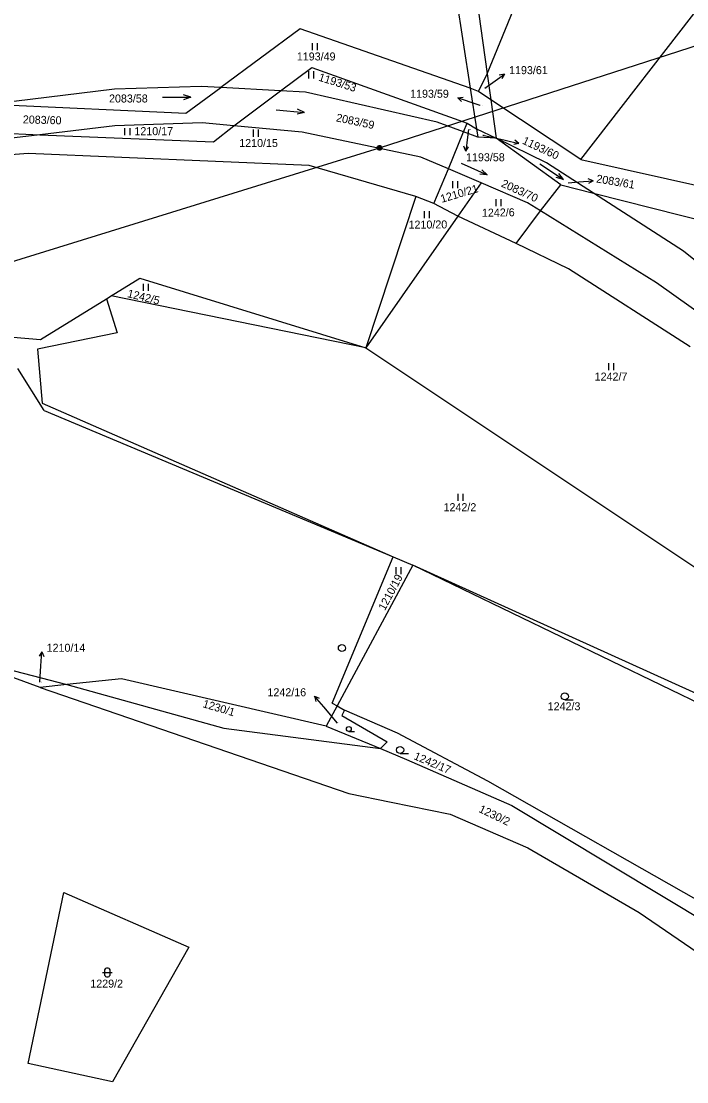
# Model space of a CAD drawing. Extents: x -795483 to -789093, y -1112258 to -1108741.
# Drawn here: x -793189.9 to -793048.5, y -1109580.4 to -1109355.1 of the extents above; entities that cross this region are included whole.
import ezdxf

# ---------------------------------------------------------------- set-up
doc = ezdxf.new("R2010")
doc.units = 0
for name, color, linetype in [('Komunikace', 7, 'Continuous'), ('Vrstva 1', 7, 'Continuous'), ('Vrstva 12', 7, 'Continuous'), ('Vrstva 14', 7, 'Continuous'), ('Vrstva 16', 7, 'Continuous'), ('Vrstva 23', 7, 'Continuous'), ('Vrstva 26', 7, 'Continuous'), ('Vrstva 28', 7, 'Continuous')]:
    doc.layers.add(name, color=color, linetype=linetype)

msp = doc.modelspace()

# ---------------------------------------------------------------- linework, layer by layer
at = {"layer": 'Komunikace'}
for p, q in [((-793091.42, -1109369.35), (-793089.69, -1109368.1)), ((-793092.43, -1109372.97), (-793094.29, -1109372.33)), ((-793094.86, -1109378.12), (-793095.08, -1109379.71)), ((-793091.81, -1109379.3), (-793087.1, -1109380.37)), ((-793073.68, -1109389.4), (-793071.42, -1109389.23)), ((-793185.98, -1109495.5), (-793185.73, -1109492.02)), ((-793122.68, -1109504.19), (-793125.65, -1109500.75))]:
    msp.add_line(p, q, dxfattribs=at)
at = {"layer": 'Vrstva 1'}
for p, q in [((-793109.65, -1109272.48), (-793094.52, -1109369.29)), ((-793103.34, -1109277.28), (-793090.93, -1109366.25)), ((-793090.93, -1109366.25), (-793070.4, -1109316.05)), ((-793071, -1109384.44), (-793038.14, -1109342.1)), ((-793130.64, -1109356.7), (-793147.51, -1109369.19)), ((-793094.52, -1109369.29), (-793130.64, -1109356.7)), ((-793134.83, -1109369.87), (-793128.2, -1109364.91)), ((-793128.2, -1109364.91), (-793095.19, -1109376.73)), ((-793092.76, -1109370), (-793090.93, -1109366.25)), ((-793090.93, -1109366.25), (-793090.16, -1109371.76)), ((-793151.71, -1109368.96), (-793170.09, -1109369.56)), ((-793154.96, -1109374.61), (-793147.51, -1109369.19)), ((-793147.51, -1109369.19), (-793151.71, -1109368.96)), ((-793134.83, -1109369.87), (-793147.51, -1109369.19)), ((-793170.09, -1109369.56), (-793196.01, -1109372.73)), ((-793144.74, -1109377.3), (-793134.83, -1109369.87)), ((-793129.54, -1109370.15), (-793134.83, -1109369.87)), ((-793101.52, -1109376.54), (-793129.54, -1109370.15)), ((-793094.52, -1109369.29), (-793093.16, -1109377.97)), ((-793092.76, -1109370), (-793094.52, -1109369.29)), ((-793090.16, -1109371.76), (-793092.76, -1109370)), ((-793196.01, -1109372.73), (-793154.96, -1109374.61)), ((-793090.16, -1109371.76), (-793089.02, -1109379.95)), ((-793071, -1109384.44), (-793090.16, -1109371.76)), ((-793224.55, -1109377.57), (-793185.96, -1109379.22)), ((-793170.03, -1109377.29), (-793185.96, -1109379.22)), ((-793151.47, -1109376.66), (-793170.03, -1109377.29)), ((-793144.74, -1109377.3), (-793151.47, -1109376.66)), ((-793149.03, -1109380.69), (-793144.74, -1109377.3)), ((-793130.22, -1109378.67), (-793144.74, -1109377.3)), ((-793095.93, -1109378.61), (-793101.52, -1109376.54)), ((-793095.93, -1109378.61), (-793095.19, -1109376.73)), ((-793095.19, -1109376.73), (-793093.16, -1109377.97)), ((-793093.16, -1109377.97), (-793092.88, -1109379.74)), ((-793093.16, -1109377.97), (-793089.02, -1109379.95)), ((-793185.96, -1109379.22), (-793204.6, -1109381.48)), ((-793185.96, -1109379.22), (-793149.03, -1109380.69)), ((-793104.99, -1109383.99), (-793130.22, -1109378.67)), ((-793099.13, -1109386.48), (-793095.93, -1109378.61)), ((-793092.88, -1109379.74), (-793095.93, -1109378.61)), ((-793089.02, -1109379.95), (-793092.88, -1109379.74)), ((-793078.31, -1109385.16), (-793089.02, -1109379.95)), ((-793075.26, -1109389.83), (-793089.02, -1109379.95)), ((-793188.43, -1109383.21), (-793222.09, -1109385.56)), ((-793128.76, -1109385.73), (-793188.43, -1109383.21)), ((-793099.13, -1109386.48), (-793104.99, -1109383.99)), ((-793071, -1109384.44), (-793037.69, -1109391.89)), ((-793106.08, -1109392.3), (-793128.76, -1109385.73)), ((-793102.27, -1109393.84), (-793099.13, -1109386.48)), ((-793092.17, -1109389.44), (-793099.13, -1109386.48)), ((-793068.32, -1109391.61), (-793078.31, -1109385.16)), ((-793092.17, -1109389.44), (-793097.13, -1109396.53)), ((-793082.37, -1109393.7), (-793092.17, -1109389.44)), ((-793079.62, -1109395.4), (-793075.26, -1109389.83)), ((-793075.26, -1109389.83), (-793068.32, -1109391.61)), ((-793068.32, -1109391.61), (-793038.71, -1109399.09)), ((-793049.2, -1109403.96), (-793068.32, -1109391.61)), ((-793106.08, -1109392.3), (-793116.71, -1109424.48)), ((-793102.27, -1109393.84), (-793106.08, -1109392.3)), ((-793097.13, -1109396.53), (-793102.27, -1109393.84)), ((-793079.62, -1109395.4), (-793082.37, -1109393.7)), ((-793084.78, -1109402.28), (-793079.62, -1109395.4)), ((-793054.96, -1109410.63), (-793079.62, -1109395.4)), ((-793097.13, -1109396.53), (-793116.71, -1109424.48)), ((-793084.78, -1109402.28), (-793097.13, -1109396.53)), ((-793073.63, -1109407.66), (-793084.78, -1109402.28)), ((-793038.01, -1109412.99), (-793049.2, -1109403.96)), ((-793170.77, -1109413.41), (-793164.7, -1109409.66)), ((-793164.7, -1109409.66), (-793116.71, -1109424.48)), ((-793047.81, -1109424.26), (-793073.63, -1109407.66)), ((-793043.91, -1109418.54), (-793054.96, -1109410.63)), ((-793185.83, -1109422.72), (-793171.82, -1109414.06)), ((-793171.82, -1109414.06), (-793170.77, -1109413.41)), ((-793171.82, -1109414.06), (-793169.53, -1109421.28)), ((-793116.71, -1109424.48), (-793170.77, -1109413.41)), ((-793220.88, -1109419.57), (-793185.83, -1109422.72)), ((-793169.53, -1109421.28), (-793186.44, -1109424.78)), ((-793186.44, -1109424.78), (-793185.46, -1109436.23)), ((-793116.71, -1109424.48), (-793016.28, -1109491.44)), ((-793185, -1109437.79), (-793190.59, -1109428.89)), ((-793185.46, -1109436.23), (-793110.88, -1109468.89)), ((-793185, -1109437.79), (-793110.88, -1109468.89)), ((-793123.85, -1109499.95), (-793110.88, -1109468.89)), ((-793110.88, -1109468.89), (-793106.73, -1109470.63)), ((-793106.73, -1109470.63), (-793122.78, -1109500.53)), ((-793024.95, -1109510.11), (-793106.73, -1109470.63)), ((-793022.18, -1109508.97), (-793106.73, -1109470.63)), ((-793185.88, -1109496.6), (-793206.38, -1109489.13)), ((-793206.38, -1109489.13), (-793180.21, -1109496.01)), ((-793168.6, -1109494.8), (-793180.21, -1109496.01)), ((-793125.1, -1109504.86), (-793168.6, -1109494.8)), ((-793180.21, -1109496.01), (-793185.88, -1109496.6)), ((-793185.88, -1109496.6), (-793120.27, -1109519.16)), ((-793180.21, -1109496.01), (-793146.83, -1109505.23)), ((-793122.78, -1109500.53), (-793125.1, -1109504.86)), ((-793123.85, -1109499.95), (-793122.78, -1109500.53)), ((-793122.78, -1109500.53), (-793121.26, -1109501.46)), ((-793121.26, -1109501.46), (-793121.8, -1109502.58)), ((-793109.95, -1109506.33), (-793121.26, -1109501.46)), ((-793121.8, -1109502.58), (-793112.15, -1109508.18)), ((-793146.83, -1109505.23), (-793113.56, -1109509.61)), ((-793125.1, -1109504.86), (-793113.56, -1109509.61)), ((-793090.8, -1109516.53), (-793109.95, -1109506.33)), ((-793112.15, -1109508.18), (-793113.56, -1109509.61)), ((-793113.56, -1109509.61), (-793108.04, -1109511.89)), ((-793108.04, -1109511.89), (-793085.67, -1109521.66)), ((-793037.96, -1109546.51), (-793090.8, -1109516.53)), ((-793120.27, -1109519.16), (-793111.33, -1109520.99)), ((-793111.33, -1109520.99), (-793098.78, -1109523.55)), ((-793085.67, -1109521.66), (-793039.11, -1109549.74)), ((-793098.78, -1109523.55), (-793082.25, -1109530.69)), ((-793082.25, -1109530.69), (-793058.59, -1109544.44)), ((-793188.41, -1109576.45), (-793180.87, -1109540.17)), ((-793180.87, -1109540.17), (-793154.31, -1109551.77)), ((-793058.59, -1109544.44), (-793041.11, -1109556.39)), ((-793154.31, -1109551.77), (-793170.52, -1109580.37)), ((-793170.52, -1109580.37), (-793188.41, -1109576.45))]:
    msp.add_line(p, q, dxfattribs=at)
at = {"layer": 'Vrstva 12'}
for p, q in [((-793113.78, -1109381.98), (-792993.86, -1109343.29)), ((-793240.53, -1109421.21), (-793113.78, -1109381.98))]:
    msp.add_line(p, q, dxfattribs=at)
at = {"layer": 'Vrstva 16'}
for p, q in [((-793089.69, -1109368.1), (-793087.26, -1109366.34)), ((-793087.26, -1109366.34), (-793088.36, -1109366.52)), ((-793087.26, -1109366.34), (-793087.78, -1109367.33)), ((-793097.13, -1109371.35), (-793096.02, -1109371.21)), ((-793094.29, -1109372.33), (-793097.13, -1109371.35)), ((-793097.13, -1109371.35), (-793096.34, -1109372.15)), ((-793095.08, -1109379.71), (-793095.48, -1109382.68)), ((-793087.1, -1109380.37), (-793084.18, -1109381.04)), ((-793084.18, -1109381.04), (-793085.04, -1109380.33)), ((-793095.48, -1109382.68), (-793095.84, -1109381.62)), ((-793095.48, -1109382.68), (-793094.85, -1109381.76)), ((-793084.18, -1109381.04), (-793085.26, -1109381.3)), ((-793071.42, -1109389.23), (-793068.43, -1109389.01)), ((-793068.43, -1109389.01), (-793069.46, -1109388.58)), ((-793068.43, -1109389.01), (-793069.39, -1109389.58)), ((-793185.51, -1109489.03), (-793186.08, -1109489.99)), ((-793185.73, -1109492.02), (-793185.51, -1109489.03)), ((-793185.51, -1109489.03), (-793185.09, -1109490.06)), ((-793125.65, -1109500.75), (-793127.61, -1109498.48)), ((-793127.61, -1109498.48), (-793127.33, -1109499.56)), ((-793127.61, -1109498.48), (-793126.58, -1109498.91))]:
    msp.add_line(p, q, dxfattribs=at)
at = {"layer": 'Vrstva 23'}
for p, q in [((-793128.04, -1109361.23), (-793128.04, -1109359.73)), ((-793127.04, -1109359.73), (-793127.04, -1109361.23)), ((-793128.8, -1109367.24), (-793128.8, -1109365.74)), ((-793127.8, -1109365.74), (-793127.8, -1109367.24)), ((-793159.9, -1109371.26), (-793153.9, -1109371.26)), ((-793153.9, -1109371.26), (-793155.4, -1109370.76)), ((-793153.9, -1109371.26), (-793155.4, -1109371.76)), ((-793135.73, -1109373.89), (-793129.75, -1109374.45)), ((-793129.75, -1109374.45), (-793131.29, -1109374.81)), ((-793129.75, -1109374.45), (-793131.2, -1109373.81)), ((-793167.86, -1109379.3), (-793167.86, -1109377.8)), ((-793166.86, -1109377.8), (-793166.86, -1109379.3)), ((-793140.54, -1109379.62), (-793140.54, -1109378.12)), ((-793139.54, -1109378.12), (-793139.54, -1109379.62)), ((-793096.41, -1109385.28), (-793090.91, -1109387.7)), ((-793090.91, -1109387.7), (-793092.08, -1109386.64)), ((-793079.72, -1109385.39), (-793074.72, -1109388.69)), ((-793098.24, -1109390.56), (-793098.24, -1109389.06)), ((-793097.24, -1109389.06), (-793097.24, -1109390.56)), ((-793090.91, -1109387.7), (-793092.49, -1109387.55)), ((-793074.72, -1109388.69), (-793076.24, -1109388.28)), ((-793074.72, -1109388.69), (-793075.69, -1109387.45)), ((-793088.99, -1109394.38), (-793088.99, -1109392.88)), ((-793087.99, -1109392.88), (-793087.99, -1109394.38)), ((-793104.21, -1109396.94), (-793104.21, -1109395.44)), ((-793103.21, -1109395.44), (-793103.21, -1109396.94)), ((-793163.95, -1109412.38), (-793163.95, -1109410.88)), ((-793162.95, -1109410.88), (-793162.95, -1109412.38)), ((-793065.06, -1109429.23), (-793065.06, -1109427.73)), ((-793064.06, -1109427.73), (-793064.06, -1109429.23)), ((-793097.06, -1109456.97), (-793097.06, -1109455.47)), ((-793096.06, -1109455.47), (-793096.06, -1109456.97)), ((-793110.27, -1109472.53), (-793110.27, -1109471.03)), ((-793109.27, -1109471.03), (-793109.27, -1109472.53)), ((-793074.42, -1109499.26), (-793072.67, -1109499.26)), ((-793120.31, -1109505.96), (-793119.08, -1109505.96)), ((-793109.4, -1109510.64), (-793107.65, -1109510.64)), ((-793171.91, -1109556.27), (-793171.71, -1109556.17)), ((-793171.71, -1109556.17), (-793171.51, -1109556.17)), ((-793171.51, -1109556.17), (-793171.31, -1109556.27)), ((-793172.61, -1109557.17), (-793170.61, -1109557.17)), ((-793172.11, -1109556.57), (-793172.01, -1109556.37)), ((-793172.11, -1109557.77), (-793172.11, -1109556.57)), ((-793172.01, -1109557.97), (-793172.11, -1109557.77)), ((-793172.01, -1109556.37), (-793171.91, -1109556.27)), ((-793171.91, -1109558.07), (-793172.01, -1109557.97)), ((-793171.71, -1109558.17), (-793171.91, -1109558.07)), ((-793171.51, -1109558.17), (-793171.71, -1109558.17)), ((-793171.31, -1109558.07), (-793171.51, -1109558.17)), ((-793171.31, -1109556.27), (-793171.21, -1109556.37)), ((-793171.21, -1109557.97), (-793171.31, -1109558.07)), ((-793171.21, -1109556.37), (-793171.11, -1109556.57)), ((-793171.11, -1109557.77), (-793171.21, -1109557.97)), ((-793171.11, -1109556.57), (-793171.11, -1109557.77))]:
    msp.add_line(p, q, dxfattribs=at)
for centre, radius in [((-793074.42, -1109498.51), 0.75), ((-793120.31, -1109505.44), 0.525), ((-793109.4, -1109509.89), 0.75)]:
    msp.add_circle(centre, radius, dxfattribs=at)
at = {"layer": 'Vrstva 26'}
for p, q in [((-793114.28, -1109381.88), (-793114.18, -1109381.68)), ((-793114.28, -1109381.88), (-793114.18, -1109381.68)), ((-793114.28, -1109382.08), (-793114.28, -1109381.88)), ((-793114.28, -1109382.08), (-793114.28, -1109381.88)), ((-793114.18, -1109382.28), (-793114.28, -1109382.08)), ((-793114.18, -1109382.28), (-793114.28, -1109382.08)), ((-793114.18, -1109381.68), (-793114.08, -1109381.58)), ((-793114.18, -1109381.68), (-793114.08, -1109381.58)), ((-793114.08, -1109382.38), (-793114.18, -1109382.28)), ((-793114.08, -1109382.38), (-793114.18, -1109382.28)), ((-793114.08, -1109381.58), (-793113.88, -1109381.48)), ((-793114.08, -1109381.58), (-793113.88, -1109381.48)), ((-793114.08, -1109381.78), (-793114.08, -1109382.18)), ((-793114.08, -1109381.78), (-793114.08, -1109382.18)), ((-793114.08, -1109382.18), (-793113.88, -1109382.28)), ((-793114.08, -1109382.18), (-793113.88, -1109382.28)), ((-793113.88, -1109382.48), (-793114.08, -1109382.38)), ((-793113.88, -1109382.48), (-793114.08, -1109382.38)), ((-793113.88, -1109381.48), (-793113.68, -1109381.48)), ((-793113.88, -1109381.48), (-793113.68, -1109381.48)), ((-793113.88, -1109382.28), (-793113.88, -1109381.68)), ((-793113.88, -1109381.68), (-793113.68, -1109381.68)), ((-793113.88, -1109382.28), (-793113.88, -1109381.68)), ((-793113.88, -1109381.68), (-793113.68, -1109381.68)), ((-793113.68, -1109382.48), (-793113.88, -1109382.48)), ((-793113.68, -1109382.48), (-793113.88, -1109382.48)), ((-793113.68, -1109381.48), (-793113.48, -1109381.58)), ((-793113.68, -1109381.48), (-793113.48, -1109381.58)), ((-793113.68, -1109381.68), (-793113.68, -1109382.28)), ((-793113.68, -1109381.68), (-793113.68, -1109382.28)), ((-793113.68, -1109382.28), (-793113.48, -1109382.18)), ((-793113.68, -1109382.28), (-793113.48, -1109382.18)), ((-793113.48, -1109382.38), (-793113.68, -1109382.48)), ((-793113.48, -1109382.38), (-793113.68, -1109382.48)), ((-793113.48, -1109381.58), (-793113.38, -1109381.68)), ((-793113.48, -1109381.58), (-793113.38, -1109381.68)), ((-793113.48, -1109382.18), (-793113.48, -1109381.78)), ((-793113.48, -1109382.18), (-793113.48, -1109381.78)), ((-793113.38, -1109382.28), (-793113.48, -1109382.38)), ((-793113.38, -1109382.28), (-793113.48, -1109382.38)), ((-793113.38, -1109381.68), (-793113.28, -1109381.88)), ((-793113.38, -1109381.68), (-793113.28, -1109381.88)), ((-793113.28, -1109382.08), (-793113.38, -1109382.28)), ((-793113.28, -1109382.08), (-793113.38, -1109382.28)), ((-793113.28, -1109381.88), (-793113.28, -1109382.08)), ((-793113.28, -1109381.88), (-793113.28, -1109382.08))]:
    msp.add_line(p, q, dxfattribs=at)
at = {"layer": 'Vrstva 28'}
for radius in [0.75, 0.01]:
    msp.add_circle((-793121.78, -1109488.24), radius, dxfattribs=at)

# ---------------------------------------------------------------- texts
at = {"layer": 'Vrstva 14'}
for s, height, p in [('1193/49', 1.7, (-793131.35, -1109363.43)), ('2083/58', 1.7, (-793171.25, -1109372.36)), ('1193/61', 0.1, (-793091.42, -1109369.35)), ('1193/59', 0.1, (-793092.43, -1109372.97)), ('1210/17', 1.7, (-793165.86, -1109379.3)), ('1193/58', 0.1, (-793094.86, -1109378.12)), ('1210/15', 1.7, (-793143.59, -1109381.82)), ('1193/60', 0.1, (-793091.81, -1109379.3)), ('2083/61', 0.1, (-793073.68, -1109389.4)), ('1242/7', 1.7, (-793068.08, -1109431.43)), ('1242/2', 1.7, (-793100.18, -1109459.17)), ('1210/14', 0.1, (-793185.98, -1109495.5)), ('1242/3', 1.7, (-793078.06, -1109501.46)), ('1242/16', 0.1, (-793122.68, -1109504.19)), ('1229/2', 1.7, (-793175.23, -1109560.37))]:
    msp.add_text(s, height=height, dxfattribs=at).set_placement(p)
for s, rotation, p in [('1193/53', 342.6778, (-793126.87, -1109367.69)), ('2083/60', 358.4639, (-793189.58, -1109376.79)), ('2083/59', 348.1199, (-793123.12, -1109376.34)), ('2083/70', 335.3432, (-793088.07, -1109390.16)), ('1210/21', 16.414, (-793100.55, -1109393.68)), ('1242/6', 1.1065, (-793092.01, -1109396.65)), ('1210/20', 0.3774, (-793107.61, -1109399.16)), ('1242/5', 346.4757, (-793167.47, -1109413.68)), ('1210/19', 62.0042, (-793112.64, -1109480.4)), ('1230/1', 343.4626, (-793151.47, -1109500.78)), ('1242/17', 337.0362, (-793106.64, -1109511.81)), ('1230/2', 334.2853, (-793092.84, -1109523))]:
    msp.add_text(s, height=1.7, rotation=rotation, dxfattribs=at).set_placement(p)
at = {"layer": 'Vrstva 16'}
for s, p in [('1193/61', (-793086.26, -1109366.34)), ('1193/59', (-793107.28, -1109371.35)), ('1193/58', (-793095.4, -1109384.84)), ('1210/14', (-793184.51, -1109489.03)), ('1242/16', (-793137.59, -1109498.48))]:
    msp.add_text(s, height=1.7, dxfattribs=at).set_placement(p)
for s, rotation, p in [('1193/60', 334.7989, (-793083.6, -1109381.04)), ('2083/61', 350.3688, (-793067.82, -1109389.32))]:
    msp.add_text(s, height=1.7, rotation=rotation, dxfattribs=at).set_placement(p)

doc.saveas('drawing.dxf')
